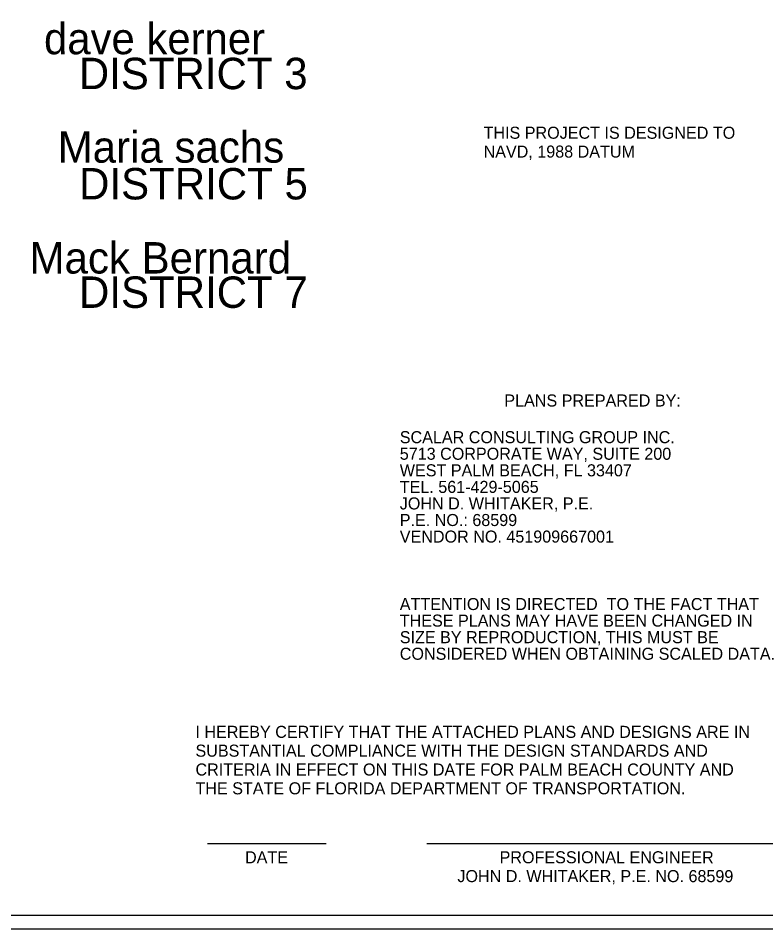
# Model space of a CAD drawing. Extents: x 801329 to 1179195, y 842463 to 1027285.
# Drawn here: x 968094 to 1052425, y 842463 to 945233 of the extents above; entities that cross this region are included whole.
import ezdxf

# ---------------------------------------------------------------- set-up
doc = ezdxf.new("R2010")
doc.units = 0
for name, color, linetype in [('Default', 7, 'Continuous'), ('PlotBorder_dp', 7, 'Continuous'), ('TextLabel', 7, 'Continuous')]:
    doc.layers.add(name, color=color, linetype=linetype)

msp = doc.modelspace()

# ---------------------------------------------------------------- linework, layer by layer
at = {"layer": 'Default'}
for p, q in [((989461, 852087), (1002832, 852087)), ((1014202, 852087), (1055517, 852087)), ((1063315, 843950), (813867, 843950))]:
    msp.add_line(p, q, dxfattribs=at)
at = {"layer": 'PlotBorder_dp'}
msp.add_lwpolyline([(801329, 842463), (1085229, 842463), (1085229, 1022663), (801329, 1022663)], close=True, dxfattribs=at)

# ---------------------------------------------------------------- texts
at = {"layer": 'Default'}
for s, p in [('THIS PROJECT IS DESIGNED TO', (1020586, 931627)), ('NAVD, 1988 DATUM', (1020586, 929502)), ('PLANS PREPARED BY:', (1022932, 901408)), ('SCALAR CONSULTING GROUP INC.', (1011136, 897268)), ('5713 CORPORATE WAY, SUITE 200', (1011136, 895398)), ('WEST PALM BEACH, FL 33407', (1011136, 893528)), ('TEL. 561-429-5065', (1011136, 891658)), ('JOHN D. WHITAKER, P.E.', (1011136, 889788)), ('P.E. NO.: 68599', (1011136, 887918)), ('VENDOR NO. 451909667001', (1011136, 886048)), ('ATTENTION IS DIRECTED  TO THE FACT THAT', (1011136, 878435)), ('THESE PLANS MAY HAVE BEEN CHANGED IN', (1011136, 876565)), ('SIZE BY REPRODUCTION, THIS MUST BE', (1011136, 874695)), ('CONSIDERED WHEN OBTAINING SCALED DATA.', (1011136, 872825)), ('I HEREBY CERTIFY THAT THE ATTACHED PLANS AND DESIGNS ARE IN', (988091, 864011)), ('SUBSTANTIAL COMPLIANCE WITH THE DESIGN STANDARDS AND', (988091, 861886)), ('CRITERIA IN EFFECT ON THIS DATE FOR PALM BEACH COUNTY AND', (988091, 859761)), ('THE STATE OF FLORIDA DEPARTMENT OF TRANSPORTATION.', (988091, 857636)), ('DATE', (993681, 849853)), ('PROFESSIONAL ENGINEER', (1022396, 849853)), ('JOHN D. WHITAKER, P.E. NO. 68599', (1017637, 847728))]:
    msp.add_text(s, height=1360, dxfattribs=at).set_placement(p)
at = {"layer": 'TextLabel'}
for s, height, p in [('dave kerner', 3531.23, (971005, 941169)), ('DISTRICT 3', 3544.7, (974928, 937225)), ('Maria sachs', 3544.7, (972548, 928929)), ('DISTRICT 5', 3544.3, (974961, 924781)), ('DISTRICT 7', 3544.7, (974949, 912541))]:
    msp.add_text(s, height=height, rotation=360, dxfattribs=at).set_placement(p)
msp.add_text('Mack Bernard', height=3544.49, dxfattribs=at).set_placement((969372, 916417))

doc.saveas('drawing.dxf')
